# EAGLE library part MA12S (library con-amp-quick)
AMP QUICK CONNECTOR
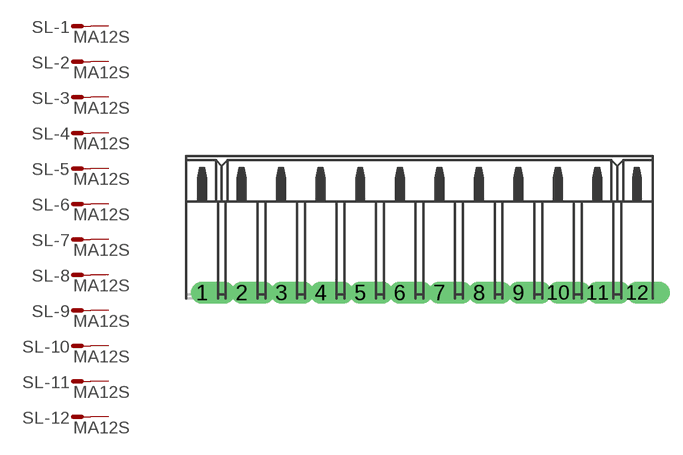
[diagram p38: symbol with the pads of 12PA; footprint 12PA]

Designator prefix SL; gates -1=M -2=M -3=M -4=M -5=M -6=M -7=M -8=M -9=M -10=M -11=M -12=M

## MA12S  [12PA]
1  -1:S  pas
2  -2:S  pas
3  -3:S  pas
4  -4:S  pas
5  -5:S  pas
6  -6:S  pas
7  -7:S  pas
8  -8:S  pas
9  -9:S  pas
10  -10:S  pas
11  -11:S  pas
12  -12:S  pas

## Footprint 12PA (pad centres in mm)
AMP QUICK CONNECTOR
drill 0.914 offset: 1 -13.97,0; 2 -11.43,0; 3 -8.89,0; 4 -6.35,0; 5 -3.81,0; 6 -1.27,0; 7 1.27,0; 8 3.81,0; 9 6.35,0; 10 8.89,0; 11 11.43,0; 12 13.97,0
